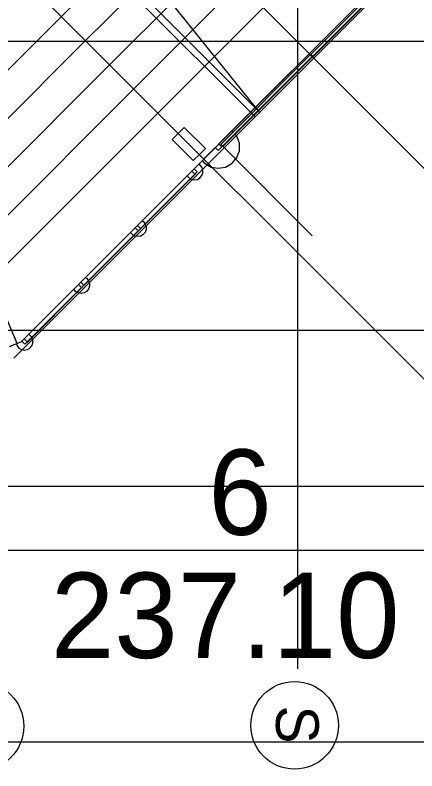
# Model space of a CAD drawing. Extents: x -264165 to -263575, y -1242333 to -1242036.
# Drawn here: x -263808.94 to -263799.51, y -1242251.13 to -1242233.41 of the extents above; entities that cross this region are included whole.
import ezdxf

# ---------------------------------------------------------------- set-up
doc = ezdxf.new("R2010")
doc.units = 0
for name, color, linetype in [('KFA_BODY_VYTYCOVAK', 7, 'Continuous'), ('KFA_HESCON_OSI_STAVBY', 7, 'Continuous'), ('KFA_SITUACIA_DRS_VYTYCOVAK_SEDA', 7, 'Continuous')]:
    doc.layers.add(name, color=color, linetype=linetype)

msp = doc.modelspace()

# ---------------------------------------------------------------- linework, layer by layer
at = {"layer": 'KFA_HESCON_OSI_STAVBY'}
for p, q in [((-263802.318, -1242080.447), (-263802.318, -1242248.737)), ((-263819.468, -1242216.882), (-263794.893, -1242241.457)), ((-263797.368, -1242243.932), (-263815.42, -1242225.879)), ((-263787.486, -1242234.032), (-263921.823, -1242234.032)), ((-263787.486, -1242240.807), (-263921.823, -1242240.807))]:
    msp.add_line(p, q, dxfattribs=at)
for centre, radius in [((-263809.783, -1242250.084), 1.047), ((-263802.383, -1242250.064), 1.027)]:
    msp.add_circle(centre, radius, dxfattribs=at)
at = {"layer": 'KFA_SITUACIA_DRS_VYTYCOVAK_SEDA'}
for p, q in [((-263803.204, -1242235.693), (-263813.678, -1242222.657)), ((-263794.893, -1242227.382), (-263808.968, -1242241.457)), ((-263807.852, -1242233.447), (-263802.903, -1242228.498)), ((-263807.852, -1242233.447), (-263802.903, -1242228.498)), ((-263802.337, -1242229.063), (-263807.287, -1242234.013)), ((-263802.337, -1242229.063), (-263807.287, -1242234.013)), ((-263806.721, -1242234.579), (-263801.771, -1242229.629)), ((-263806.721, -1242234.579), (-263801.771, -1242229.629)), ((-263806.155, -1242235.145), (-263801.206, -1242230.195)), ((-263806.155, -1242235.145), (-263801.206, -1242230.195)), ((-263800.64, -1242230.76), (-263805.59, -1242235.71)), ((-263800.64, -1242230.76), (-263805.59, -1242235.71)), ((-263807.987, -1242230.91), (-263803.204, -1242235.693)), ((-263808.093, -1242231.016), (-263803.31, -1242235.799)), ((-263804.511, -1242236.789), (-263799.561, -1242231.839)), ((-263804.511, -1242236.789), (-263799.561, -1242231.839)), ((-263799.915, -1242232.192), (-263804.158, -1242236.435)), ((-263799.915, -1242232.192), (-263804.158, -1242236.435)), ((-263802.001, -1242234.335), (-263799.904, -1242232.238)), ((-263802.001, -1242234.335), (-263799.904, -1242232.238)), ((-263799.862, -1242232.281), (-263801.959, -1242234.377)), ((-263799.862, -1242232.281), (-263801.959, -1242234.377)), ((-263799.884, -1242232.302), (-263801.941, -1242234.359)), ((-263799.884, -1242232.302), (-263801.941, -1242234.359)), ((-263801.934, -1242234.366), (-263799.877, -1242232.309)), ((-263801.934, -1242234.366), (-263799.877, -1242232.309)), ((-263810.987, -1242236.582), (-263807.852, -1242233.447)), ((-263810.987, -1242236.582), (-263807.852, -1242233.447)), ((-263807.287, -1242234.013), (-263810.656, -1242237.382)), ((-263807.287, -1242234.013), (-263810.656, -1242237.382)), ((-263804.112, -1242236.446), (-263802.015, -1242234.349)), ((-263804.112, -1242236.446), (-263802.015, -1242234.349)), ((-263801.973, -1242234.391), (-263804.069, -1242236.488)), ((-263801.973, -1242234.391), (-263804.069, -1242236.488)), ((-263801.991, -1242234.409), (-263804.048, -1242236.466)), ((-263801.991, -1242234.409), (-263804.048, -1242236.466)), ((-263804.041, -1242236.473), (-263801.984, -1242234.416)), ((-263804.041, -1242236.473), (-263801.984, -1242234.416)), ((-263801.973, -1242234.391), (-263802.015, -1242234.349)), ((-263801.973, -1242234.391), (-263802.015, -1242234.349)), ((-263802.001, -1242234.335), (-263801.959, -1242234.377)), ((-263802.001, -1242234.335), (-263801.959, -1242234.377)), ((-263801.991, -1242234.409), (-263801.941, -1242234.359)), ((-263801.991, -1242234.409), (-263801.941, -1242234.359)), ((-263801.984, -1242234.416), (-263801.991, -1242234.409)), ((-263801.984, -1242234.416), (-263801.991, -1242234.409)), ((-263801.934, -1242234.366), (-263801.984, -1242234.416)), ((-263801.934, -1242234.366), (-263801.984, -1242234.416)), ((-263801.941, -1242234.359), (-263801.934, -1242234.366)), ((-263801.941, -1242234.359), (-263801.934, -1242234.366)), ((-263810.324, -1242238.182), (-263806.721, -1242234.579)), ((-263810.324, -1242238.182), (-263806.721, -1242234.579)), ((-263809.993, -1242238.982), (-263806.155, -1242235.145)), ((-263809.993, -1242238.982), (-263806.155, -1242235.145)), ((-263805.59, -1242235.71), (-263809.662, -1242239.782)), ((-263805.59, -1242235.71), (-263809.662, -1242239.782)), ((-263804.971, -1242236.046), (-263805.112, -1242236.187)), ((-263804.971, -1242236.046), (-263805.112, -1242236.187)), ((-263804.476, -1242236.541), (-263804.971, -1242236.046)), ((-263804.476, -1242236.541), (-263804.971, -1242236.046)), ((-263805.112, -1242236.187), (-263805.254, -1242236.329)), ((-263805.112, -1242236.187), (-263805.254, -1242236.329)), ((-263803.822, -1242236.156), (-263803.848, -1242236.125)), ((-263803.822, -1242236.156), (-263803.848, -1242236.125)), ((-263803.739, -1242236.256), (-263803.777, -1242236.21)), ((-263803.739, -1242236.256), (-263803.777, -1242236.21)), ((-263803.679, -1242236.419), (-263803.739, -1242236.256)), ((-263803.679, -1242236.419), (-263803.739, -1242236.256)), ((-263805.254, -1242236.329), (-263804.759, -1242236.824)), ((-263805.254, -1242236.329), (-263804.759, -1242236.824)), ((-263804.158, -1242236.435), (-263804.087, -1242236.506)), ((-263804.158, -1242236.435), (-263804.087, -1242236.506)), ((-263804.112, -1242236.446), (-263804.069, -1242236.488)), ((-263804.112, -1242236.446), (-263804.069, -1242236.488)), ((-263803.679, -1242236.593), (-263803.679, -1242236.419)), ((-263803.679, -1242236.593), (-263803.679, -1242236.419)), ((-263804.723, -1242237.001), (-263804.299, -1242236.576)), ((-263804.723, -1242237.001), (-263804.299, -1242236.576)), ((-263804.617, -1242236.682), (-263804.476, -1242236.541)), ((-263804.617, -1242236.682), (-263804.476, -1242236.541)), ((-263804.617, -1242236.682), (-263804.476, -1242236.541)), ((-263804.617, -1242236.682), (-263804.476, -1242236.541)), ((-263804.243, -1242236.52), (-263804.299, -1242236.576)), ((-263804.243, -1242236.52), (-263804.299, -1242236.576)), ((-263804.172, -1242236.591), (-263804.243, -1242236.52)), ((-263804.172, -1242236.591), (-263804.243, -1242236.52)), ((-263804.087, -1242236.506), (-263804.172, -1242236.591)), ((-263804.087, -1242236.506), (-263804.172, -1242236.591)), ((-263804.087, -1242236.506), (-263804.048, -1242236.466)), ((-263804.087, -1242236.506), (-263804.048, -1242236.466)), ((-263804.069, -1242236.488), (-263801.973, -1242238.585)), ((-263804.069, -1242236.488), (-263801.973, -1242238.585)), ((-263804.048, -1242236.466), (-263804.041, -1242236.473)), ((-263804.048, -1242236.466), (-263804.041, -1242236.473)), ((-263803.739, -1242236.756), (-263803.679, -1242236.593)), ((-263803.739, -1242236.756), (-263803.679, -1242236.593)), ((-263804.511, -1242236.789), (-263808.8, -1242241.078)), ((-263804.511, -1242236.789), (-263808.8, -1242241.078)), ((-263808.8, -1242241.078), (-263804.511, -1242236.789)), ((-263808.8, -1242241.078), (-263804.511, -1242236.789)), ((-263804.759, -1242236.824), (-263804.617, -1242236.682)), ((-263804.759, -1242236.824), (-263804.617, -1242236.682)), ((-263804.759, -1242236.824), (-263804.617, -1242236.682)), ((-263804.759, -1242236.824), (-263804.617, -1242236.682)), ((-263803.85, -1242236.889), (-263803.739, -1242236.756)), ((-263803.85, -1242236.889), (-263803.739, -1242236.756)), ((-263804.602, -1242236.925), (-263804.631, -1242236.908)), ((-263804.602, -1242236.925), (-263804.631, -1242236.908)), ((-263804.557, -1242236.978), (-263804.602, -1242236.925)), ((-263804.557, -1242236.978), (-263804.602, -1242236.925)), ((-263804.533, -1242237.044), (-263804.557, -1242236.978)), ((-263804.533, -1242237.044), (-263804.557, -1242236.978)), ((-263804.547, -1242236.824), (-263804.493, -1242236.889)), ((-263804.547, -1242236.824), (-263804.493, -1242236.889)), ((-263804.493, -1242236.889), (-263804.343, -1242236.976)), ((-263804.493, -1242236.889), (-263804.343, -1242236.976)), ((-263804.343, -1242236.976), (-263804.172, -1242237.006)), ((-263804.343, -1242236.976), (-263804.172, -1242237.006)), ((-263804.172, -1242237.006), (-263804.001, -1242236.976)), ((-263804.172, -1242237.006), (-263804.001, -1242236.976)), ((-263804.001, -1242236.976), (-263803.85, -1242236.889)), ((-263804.001, -1242236.976), (-263803.85, -1242236.889)), ((-263804.696, -1242237.128), (-263806.01, -1242238.443)), ((-263804.696, -1242237.128), (-263806.01, -1242238.443)), ((-263805.996, -1242238.415), (-263804.723, -1242237.142)), ((-263805.996, -1242238.415), (-263804.723, -1242237.142)), ((-263804.794, -1242237.071), (-263804.738, -1242237.015)), ((-263804.794, -1242237.071), (-263804.738, -1242237.015)), ((-263804.723, -1242237.142), (-263804.794, -1242237.071)), ((-263804.723, -1242237.142), (-263804.794, -1242237.071)), ((-263804.738, -1242237.015), (-263804.667, -1242237.086)), ((-263804.738, -1242237.015), (-263804.667, -1242237.086)), ((-263804.667, -1242237.086), (-263804.703, -1242237.121)), ((-263804.667, -1242237.086), (-263804.703, -1242237.121)), ((-263804.696, -1242237.128), (-263804.703, -1242237.121)), ((-263804.696, -1242237.128), (-263804.703, -1242237.121)), ((-263804.557, -1242237.178), (-263804.533, -1242237.113)), ((-263804.557, -1242237.178), (-263804.533, -1242237.113)), ((-263804.533, -1242237.113), (-263804.533, -1242237.044)), ((-263804.533, -1242237.113), (-263804.533, -1242237.044)), ((-263804.903, -1242237.18), (-263804.859, -1242237.232)), ((-263804.903, -1242237.18), (-263804.859, -1242237.232)), ((-263804.859, -1242237.232), (-263804.83, -1242237.249)), ((-263804.859, -1242237.232), (-263804.83, -1242237.249)), ((-263804.821, -1242237.254), (-263804.799, -1242237.266)), ((-263804.821, -1242237.254), (-263804.799, -1242237.266)), ((-263804.799, -1242237.266), (-263804.73, -1242237.278)), ((-263804.799, -1242237.266), (-263804.73, -1242237.278)), ((-263804.73, -1242237.278), (-263804.662, -1242237.266)), ((-263804.73, -1242237.278), (-263804.662, -1242237.266)), ((-263804.662, -1242237.266), (-263804.602, -1242237.232)), ((-263804.662, -1242237.266), (-263804.602, -1242237.232)), ((-263804.602, -1242237.232), (-263804.557, -1242237.178)), ((-263804.602, -1242237.232), (-263804.557, -1242237.178)), ((-263806.124, -1242238.401), (-263806.067, -1242238.344)), ((-263806.124, -1242238.401), (-263806.067, -1242238.344)), ((-263806.053, -1242238.472), (-263806.124, -1242238.401)), ((-263806.053, -1242238.472), (-263806.124, -1242238.401)), ((-263806.067, -1242238.344), (-263805.996, -1242238.415)), ((-263806.067, -1242238.344), (-263805.996, -1242238.415)), ((-263805.961, -1242238.238), (-263805.931, -1242238.255)), ((-263805.961, -1242238.238), (-263805.931, -1242238.255)), ((-263805.931, -1242238.255), (-263805.888, -1242238.307)), ((-263805.931, -1242238.255), (-263805.888, -1242238.307)), ((-263805.884, -1242238.316), (-263805.863, -1242238.373)), ((-263805.884, -1242238.316), (-263805.863, -1242238.373)), ((-263805.863, -1242238.373), (-263805.863, -1242238.443)), ((-263805.863, -1242238.373), (-263805.863, -1242238.443)), ((-263806.025, -1242238.458), (-263807.34, -1242239.772)), ((-263806.025, -1242238.458), (-263807.34, -1242239.772)), ((-263807.326, -1242239.744), (-263806.053, -1242238.472)), ((-263807.326, -1242239.744), (-263806.053, -1242238.472)), ((-263806.188, -1242238.561), (-263806.232, -1242238.509)), ((-263806.188, -1242238.561), (-263806.232, -1242238.509)), ((-263806.159, -1242238.578), (-263806.188, -1242238.561)), ((-263806.159, -1242238.578), (-263806.188, -1242238.561)), ((-263806.017, -1242238.436), (-263806.032, -1242238.451)), ((-263806.017, -1242238.436), (-263806.032, -1242238.451)), ((-263806.025, -1242238.458), (-263806.032, -1242238.451)), ((-263806.025, -1242238.458), (-263806.032, -1242238.451)), ((-263806.01, -1242238.443), (-263806.017, -1242238.436)), ((-263806.01, -1242238.443), (-263806.017, -1242238.436)), ((-263805.931, -1242238.561), (-263805.992, -1242238.596)), ((-263805.931, -1242238.561), (-263805.992, -1242238.596)), ((-263805.887, -1242238.508), (-263805.931, -1242238.561)), ((-263805.887, -1242238.508), (-263805.931, -1242238.561)), ((-263805.863, -1242238.443), (-263805.887, -1242238.508)), ((-263805.863, -1242238.443), (-263805.887, -1242238.508)), ((-263806.128, -1242238.596), (-263806.15, -1242238.583)), ((-263806.128, -1242238.596), (-263806.15, -1242238.583)), ((-263806.06, -1242238.608), (-263806.128, -1242238.596)), ((-263806.06, -1242238.608), (-263806.128, -1242238.596)), ((-263805.992, -1242238.596), (-263806.06, -1242238.608)), ((-263805.992, -1242238.596), (-263806.06, -1242238.608)), ((-263807.29, -1242239.567), (-263807.261, -1242239.584)), ((-263807.29, -1242239.567), (-263807.261, -1242239.584)), ((-263807.261, -1242239.584), (-263807.217, -1242239.636)), ((-263807.261, -1242239.584), (-263807.217, -1242239.636)), ((-263807.354, -1242239.787), (-263808.669, -1242241.102)), ((-263807.354, -1242239.787), (-263808.669, -1242241.102)), ((-263808.655, -1242241.074), (-263807.382, -1242239.801)), ((-263808.655, -1242241.074), (-263807.382, -1242239.801)), ((-263807.453, -1242239.73), (-263807.396, -1242239.674)), ((-263807.453, -1242239.73), (-263807.396, -1242239.674)), ((-263807.382, -1242239.801), (-263807.453, -1242239.73)), ((-263807.382, -1242239.801), (-263807.453, -1242239.73)), ((-263807.396, -1242239.674), (-263807.326, -1242239.744)), ((-263807.396, -1242239.674), (-263807.326, -1242239.744)), ((-263807.347, -1242239.765), (-263807.362, -1242239.78)), ((-263807.347, -1242239.765), (-263807.362, -1242239.78)), ((-263807.362, -1242239.78), (-263807.354, -1242239.787)), ((-263807.362, -1242239.78), (-263807.354, -1242239.787)), ((-263807.34, -1242239.772), (-263807.347, -1242239.765)), ((-263807.34, -1242239.772), (-263807.347, -1242239.765)), ((-263807.192, -1242239.772), (-263807.216, -1242239.837)), ((-263807.192, -1242239.772), (-263807.216, -1242239.837)), ((-263807.213, -1242239.646), (-263807.192, -1242239.703)), ((-263807.213, -1242239.646), (-263807.192, -1242239.703)), ((-263807.192, -1242239.703), (-263807.192, -1242239.772)), ((-263807.192, -1242239.703), (-263807.192, -1242239.772)), ((-263807.518, -1242239.891), (-263807.561, -1242239.839)), ((-263807.518, -1242239.891), (-263807.561, -1242239.839)), ((-263807.489, -1242239.907), (-263807.518, -1242239.891)), ((-263807.489, -1242239.907), (-263807.518, -1242239.891)), ((-263807.458, -1242239.925), (-263807.48, -1242239.913)), ((-263807.458, -1242239.925), (-263807.48, -1242239.913)), ((-263807.389, -1242239.937), (-263807.458, -1242239.925)), ((-263807.389, -1242239.937), (-263807.458, -1242239.925)), ((-263807.321, -1242239.925), (-263807.389, -1242239.937)), ((-263807.321, -1242239.925), (-263807.389, -1242239.937)), ((-263807.261, -1242239.891), (-263807.321, -1242239.925)), ((-263807.261, -1242239.891), (-263807.321, -1242239.925)), ((-263807.216, -1242239.837), (-263807.261, -1242239.891)), ((-263807.216, -1242239.837), (-263807.261, -1242239.891)), ((-263808.893, -1242241.116), (-263809.186, -1242240.407)), ((-263808.893, -1242241.116), (-263809.186, -1242240.407)), ((-263808.783, -1242241.06), (-263808.726, -1242241.003)), ((-263808.783, -1242241.06), (-263808.726, -1242241.003)), ((-263808.726, -1242241.003), (-263808.655, -1242241.074)), ((-263808.726, -1242241.003), (-263808.655, -1242241.074)), ((-263808.59, -1242240.914), (-263808.62, -1242240.897)), ((-263808.59, -1242240.914), (-263808.62, -1242240.897)), ((-263808.547, -1242240.966), (-263808.59, -1242240.914)), ((-263808.547, -1242240.966), (-263808.59, -1242240.914)), ((-263808.522, -1242241.032), (-263808.543, -1242240.975)), ((-263808.522, -1242241.032), (-263808.543, -1242240.975)), ((-263808.522, -1242241.102), (-263808.522, -1242241.032)), ((-263808.522, -1242241.102), (-263808.522, -1242241.032)), ((-263808.893, -1242241.116), (-263809.077, -1242241.192)), ((-263808.893, -1242241.116), (-263809.077, -1242241.192)), ((-263808.908, -1242241.122), (-263808.892, -1242241.167)), ((-263808.908, -1242241.122), (-263808.892, -1242241.167)), ((-263808.8, -1242241.078), (-263808.893, -1242241.116)), ((-263808.8, -1242241.078), (-263808.893, -1242241.116)), ((-263808.892, -1242241.167), (-263808.847, -1242241.22)), ((-263808.892, -1242241.167), (-263808.847, -1242241.22)), ((-263808.847, -1242241.22), (-263808.787, -1242241.255)), ((-263808.847, -1242241.22), (-263808.787, -1242241.255)), ((-263808.712, -1242241.131), (-263808.783, -1242241.06)), ((-263808.712, -1242241.131), (-263808.783, -1242241.06)), ((-263808.676, -1242241.095), (-263808.712, -1242241.131)), ((-263808.676, -1242241.095), (-263808.712, -1242241.131)), ((-263808.676, -1242241.095), (-263808.669, -1242241.102)), ((-263808.676, -1242241.095), (-263808.669, -1242241.102)), ((-263808.65, -1242241.255), (-263808.59, -1242241.22)), ((-263808.65, -1242241.255), (-263808.59, -1242241.22)), ((-263808.59, -1242241.22), (-263808.546, -1242241.167)), ((-263808.59, -1242241.22), (-263808.546, -1242241.167)), ((-263808.546, -1242241.167), (-263808.522, -1242241.102)), ((-263808.546, -1242241.167), (-263808.522, -1242241.102)), ((-263808.787, -1242241.255), (-263808.719, -1242241.267)), ((-263808.787, -1242241.255), (-263808.719, -1242241.267)), ((-263808.719, -1242241.267), (-263808.65, -1242241.255)), ((-263808.719, -1242241.267), (-263808.65, -1242241.255)), ((-263851.968, -1242244.458), (-263807.725, -1242244.458)), ((-263807.725, -1242244.458), (-263797.893, -1242244.458)), ((-263896.71, -1242245.958), (-263808.225, -1242245.958)), ((-263808.225, -1242245.958), (-263798.393, -1242245.958)), ((-263807.725, -1242250.458), (-263917.593, -1242250.458)), ((-263797.893, -1242250.458), (-263807.725, -1242250.458))]:
    msp.add_line(p, q, dxfattribs=at)

# ---------------------------------------------------------------- texts
at = {"layer": 'KFA_BODY_VYTYCOVAK'}
for s, p in [('6', (-263804.407, -1242245.597)), ('237.10', (-263808.1, -1242248.485))]:
    msp.add_text(s, height=2, dxfattribs=at).set_placement(p)
at = {"layer": 'KFA_HESCON_OSI_STAVBY'}
msp.add_text('S', height=1, rotation=270, dxfattribs=at).set_placement((-263802.818, -1242249.599))

doc.saveas('drawing.dxf')
